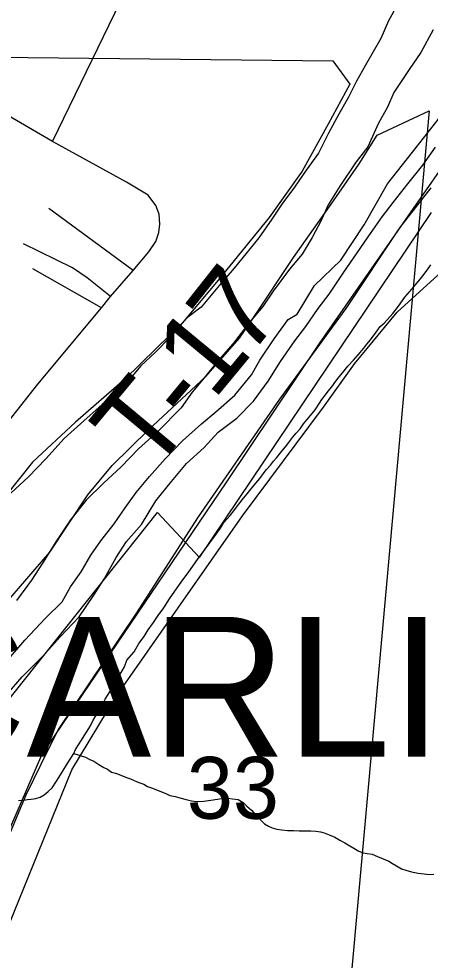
# Model space of a CAD drawing. Extents: x -7.3 to 34, y 0 to 22.
# Drawn here: x 6.491 to 6.77, y 19.077 to 19.714 of the extents above; entities that cross this region are included whole.
import ezdxf

# ---------------------------------------------------------------- set-up
doc = ezdxf.new("R2010")
doc.units = 0
for name, color, linetype in [('GM_X_Corporation', 7, 'Continuous'), ('GM_X_Corporation_Text', 7, 'Continuous'), ('GM_X_Major_River', 7, 'Continuous'), ('GM_X_Minor_River', 7, 'Continuous'), ('GM_X_Rail_Line', 7, 'Continuous'), ('GM_X_Section_Text', 7, 'Continuous'), ('GM_X_Township_Road', 7, 'Continuous'), ('GM_X_Township_Road_Text', 7, 'Continuous')]:
    doc.layers.add(name, color=color, linetype=linetype)

msp = doc.modelspace()

# ---------------------------------------------------------------- linework, layer by layer
at = {"layer": 'GM_X_Corporation'}
for points in [[(5.79575, 19.69545), (6.70378, 19.68552), (6.7152, 19.66976), (6.70064, 19.64278), (6.68296, 19.61094), (6.66075, 19.57958), (6.62618, 19.5371), (6.60174, 19.50805), (6.58435, 19.49097), (6.56271, 19.46982), (6.52956, 19.44095), (6.50061, 19.41388), (6.48197, 19.39077)], [(6.21496, 19.07117), (6.22873, 19.09665), (6.24704, 19.12166), (6.26369, 19.13988), (6.29063, 19.16131), (6.34976, 19.20102), (6.38311, 19.22119), (6.40198, 19.23633), (6.41972, 19.25226), (6.43441, 19.26712), (6.48124, 19.31692), (6.51227, 19.35305), (6.53804, 19.39192), (6.55435, 19.41166), (6.57907, 19.43578), (6.61767, 19.47174), (6.64054, 19.4978), (6.65029, 19.51199), (6.67724, 19.55236), (6.70415, 19.59083), (6.72169, 19.61585), (6.73382, 19.6353), (6.769, 19.65163), (6.71004, 18.99873)], [(5.99939, 18.48424), (6.1334, 18.89581), (6.16227, 18.87917), (6.36036, 19.15267), (6.43461, 19.19081), (6.58518, 19.37982), (6.61358, 19.34939), (6.77058, 19.58294)]]:
    msp.add_lwpolyline(points, dxfattribs=at)
at = {"layer": 'GM_X_Major_River'}
for points in [[(6.67957, 19.5142), (6.69125, 19.53359), (6.70914, 19.5506), (6.72493, 19.57451), (6.74082, 19.60221), (6.75769, 19.62381), (6.77495, 19.64578), (6.7927, 19.67229), (6.81129, 19.70144), (6.83018, 19.72793), (6.8476, 19.75597), (6.86566, 19.77981), (6.87518, 19.7959), (6.87566, 19.81411)], [(6.74739, 19.72317), (6.74143, 19.71269), (6.73618, 19.70067), (6.72586, 19.6827), (6.71989, 19.67184), (6.71429, 19.66097), (6.70792, 19.64936), (6.70077, 19.63663), (6.69397, 19.62313), (6.6857, 19.61157), (6.67782, 19.59999), (6.66917, 19.58844), (6.66246, 19.57836), (6.65379, 19.56566), (6.64479, 19.55488), (6.63695, 19.5452), (6.62717, 19.53368), (6.61465, 19.5188), (6.60459, 19.51108), (6.59364, 19.49844), (6.58351, 19.48806), (6.5738, 19.4792), (6.56205, 19.46506), (6.54771, 19.45289), (6.53528, 19.44181), (6.52208, 19.42999), (6.50959, 19.41625), (6.49789, 19.40401), (6.48585, 19.39292)], [(6.77161, 19.70662), (6.76324, 19.69126), (6.75536, 19.67969), (6.74509, 19.664), (6.74066, 19.65423), (6.73469, 19.64337), (6.72744, 19.62723), (6.7196, 19.61717), (6.70855, 19.60074), (6.70064, 19.58803), (6.69581, 19.57752), (6.68982, 19.5659), (6.68308, 19.55467), (6.67448, 19.54464), (6.66347, 19.52973), (6.65637, 19.51927), (6.64777, 19.50923), (6.63638, 19.49433), (6.62661, 19.48319), (6.61681, 19.4709), (6.6086, 19.46123), (6.60112, 19.45079), (6.58554, 19.43485), (6.57233, 19.42303), (6.56064, 19.41079), (6.5486, 19.3997), (6.53692, 19.38822), (6.52633, 19.37481), (6.51686, 19.36062), (6.50737, 19.34567), (6.49986, 19.33409), (6.48965, 19.32029)], [(6.48345, 19.25702), (6.49361, 19.26854), (6.50762, 19.28262), (6.51934, 19.29562), (6.53221, 19.30935), (6.54207, 19.32391), (6.54919, 19.33512), (6.55714, 19.34936), (6.56425, 19.36019), (6.57441, 19.37171), (6.58393, 19.3878), (6.59451, 19.40083), (6.60469, 19.4131), (6.61672, 19.42381), (6.62609, 19.43421), (6.63886, 19.44376), (6.65015, 19.45525), (6.65998, 19.46868), (6.6683, 19.48214), (6.67814, 19.49594), (6.6856, 19.50563), (6.69388, 19.51795), (6.70134, 19.52764), (6.71121, 19.54258), (6.71987, 19.55489), (6.72776, 19.56646), (6.73721, 19.5799), (6.74466, 19.58958), (6.75447, 19.60225), (6.76466, 19.6149), (6.77333, 19.62721)], [(6.52072, 19.31951), (6.52629, 19.32962), (6.53338, 19.3397), (6.54012, 19.35092), (6.54682, 19.36063), (6.55584, 19.37217), (6.56333, 19.383), (6.57081, 19.39345), (6.57981, 19.40423), (6.59036, 19.41612), (6.60205, 19.42836), (6.61486, 19.43981), (6.62456, 19.44792), (6.63737, 19.45937), (6.64872, 19.47314), (6.65429, 19.48287), (6.66415, 19.49743), (6.67359, 19.51048), (6.67957, 19.5142)], [(6.27448, 19.06705), (6.28426, 19.0782), (6.29135, 19.08866), (6.29961, 19.09985), (6.30862, 19.11102), (6.31839, 19.12216), (6.32703, 19.13334), (6.33524, 19.14301), (6.34541, 19.15491), (6.35866, 19.16863), (6.36995, 19.17974), (6.38387, 19.1904), (6.39436, 19.20001), (6.40402, 19.20661), (6.41841, 19.22068), (6.42809, 19.22803), (6.43856, 19.23726), (6.44823, 19.24424), (6.4607, 19.25721), (6.47041, 19.26609), (6.48288, 19.27906), (6.4954, 19.29356), (6.50943, 19.3084), (6.52072, 19.31951)]]:
    msp.add_lwpolyline(points, dxfattribs=at)
at = {"layer": 'GM_X_Minor_River'}
for points in [[(6.72096, 19.48665), (6.72485, 19.49113), (6.72681, 19.49374), (6.72915, 19.49673), (6.73305, 19.50197), (6.73579, 19.50571), (6.73849, 19.50793), (6.74433, 19.51465), (6.74823, 19.5195), (6.75253, 19.52549), (6.7572, 19.53109), (6.76188, 19.53669), (6.76461, 19.54005), (6.76695, 19.54304), (6.77008, 19.54753)], [(6.49101, 19.18495), (6.49443, 19.18525), (6.49709, 19.18558), (6.49975, 19.1859), (6.50279, 19.18621), (6.50585, 19.18728), (6.50854, 19.18875), (6.51124, 19.19097), (6.51395, 19.19357), (6.5167, 19.19807), (6.52063, 19.20407), (6.52456, 19.21044), (6.52849, 19.21682), (6.52968, 19.21945), (6.53362, 19.22583), (6.53558, 19.22883), (6.53872, 19.2337), (6.54029, 19.23633), (6.54149, 19.23896), (6.54306, 19.24159), (6.54582, 19.24647), (6.5474, 19.24909), (6.54977, 19.2536), (6.55291, 19.25848), (6.55529, 19.26337), (6.55843, 19.26824), (6.56118, 19.27274), (6.56276, 19.27537), (6.56437, 19.27989), (6.56943, 19.28548), (6.57258, 19.29111), (6.5761, 19.29598), (6.57886, 19.30048), (6.58238, 19.30534), (6.58552, 19.31022), (6.58942, 19.31545), (6.59334, 19.32145), (6.59687, 19.32669), (6.60118, 19.33268), (6.60626, 19.33979), (6.61213, 19.34802), (6.61799, 19.35588), (6.62307, 19.36261), (6.62776, 19.36934), (6.63012, 19.37309), (6.6344, 19.37794), (6.63674, 19.38093), (6.63869, 19.38355), (6.64103, 19.38654), (6.64337, 19.38953), (6.64571, 19.39252), (6.64844, 19.39588), (6.65156, 19.39961), (6.65429, 19.40297), (6.65663, 19.40596), (6.65897, 19.40895), (6.66169, 19.41193), (6.66364, 19.41455), (6.66597, 19.41716), (6.66831, 19.42015), (6.6726, 19.42538), (6.67455, 19.42799), (6.67651, 19.43061), (6.67885, 19.4336), (6.68157, 19.43658), (6.68392, 19.43995), (6.68625, 19.44256), (6.68859, 19.44555), (6.6917, 19.44929), (6.69484, 19.45378), (6.69641, 19.4564), (6.69875, 19.45939), (6.7007, 19.46201), (6.70304, 19.465), (6.70578, 19.46874), (6.70812, 19.47173), (6.71046, 19.47472), (6.71397, 19.47882), (6.71785, 19.48292), (6.72096, 19.48665)], [(6.52849, 19.21682), (6.5364, 19.21437), (6.5394, 19.21278), (6.54203, 19.21159), (6.54539, 19.20923), (6.54876, 19.20726), (6.55139, 19.20606), (6.55401, 19.20411), (6.5574, 19.20327), (6.56041, 19.20207), (6.56417, 19.20047), (6.5668, 19.19965), (6.56943, 19.19845), (6.57244, 19.19725), (6.57583, 19.19603), (6.57845, 19.19446), (6.58109, 19.19364), (6.58409, 19.19243), (6.58785, 19.19083), (6.59086, 19.18963), (6.59349, 19.18843), (6.59726, 19.18759), (6.60028, 19.18676), (6.60443, 19.18553), (6.6082, 19.18469), (6.61198, 19.18423), (6.61654, 19.18451), (6.62111, 19.18517), (6.62567, 19.18583), (6.62986, 19.18651), (6.63289, 19.18644), (6.63592, 19.18599), (6.6397, 19.18553), (6.64307, 19.18356), (6.64568, 19.18122), (6.64865, 19.1785), (6.65124, 19.1754), (6.65383, 19.17268), (6.65755, 19.16918), (6.66017, 19.16761), (6.6628, 19.16641), (6.66582, 19.16558), (6.66922, 19.16513), (6.67301, 19.16467), (6.67717, 19.16458), (6.68097, 19.1645), (6.68476, 19.16441), (6.68893, 19.16432), (6.69234, 19.16425), (6.69536, 19.1638), (6.698, 19.16299), (6.70139, 19.16178), (6.70515, 19.16017), (6.70852, 19.1582), (6.71189, 19.15623), (6.71526, 19.15425), (6.71788, 19.15268), (6.72125, 19.1507), (6.72426, 19.1495), (6.7269, 19.14906), (6.73031, 19.14861), (6.73407, 19.14701), (6.73782, 19.1454), (6.74158, 19.1438), (6.7442, 19.14223), (6.74682, 19.14065), (6.75019, 19.13868), (6.75321, 19.13785), (6.75698, 19.13663), (6.76151, 19.13577), (6.76567, 19.1353), (6.7687, 19.13486), (6.77212, 19.13516)]]:
    msp.add_lwpolyline(points, dxfattribs=at)
at = {"layer": 'GM_X_Rail_Line'}
for points in [[(5.86797, 17.82074), (5.95555, 17.97549), (6.08542, 18.19238), (6.10492, 18.22068), (6.19066, 18.52974), (6.2198, 18.58306), (6.37494, 18.91122), (6.50682, 19.2158), (6.63202, 19.40065), (6.69473, 19.49419), (6.79703, 19.64123), (6.94893, 19.86408), (6.97314, 19.90133), (7.00068, 19.98662)], [(6.23157, 18.56872), (6.25767, 18.62602), (6.30717, 18.73097), (6.35546, 18.82795), (6.3734, 18.85699), (6.38927, 18.87642), (6.41374, 18.91463), (6.45578, 19.03), (6.52725, 19.20568), (6.55721, 19.25523), (6.64261, 19.37772), (6.6974, 19.45125), (6.71851, 19.48043), (6.74726, 19.51536), (6.77489, 19.54041), (6.79714, 19.55888), (6.84936, 19.61297), (6.90337, 19.68298), (6.93396, 19.73922)]]:
    msp.add_lwpolyline(points, dxfattribs=at)
at = {"layer": 'GM_X_Township_Road'}
for p, q in [((6.56859, 19.54358), (6.51156, 19.58552)), ((6.54716, 19.51839), (6.50074, 19.54466))]:
    msp.add_line(p, q, dxfattribs=at)
for points in [[(6.51417, 19.63105), (6.55624, 19.71779), (6.57955, 19.76757), (6.59575, 19.80075), (6.60444, 19.82129), (6.60701, 19.83571), (6.60977, 19.95758)], [(6.47774, 19.43369), (6.484, 19.44131), (6.5042, 19.46674), (6.54716, 19.51839), (6.55338, 19.526), (6.56859, 19.54358), (6.57926, 19.55632), (6.5839, 19.56333), (6.58607, 19.56926), (6.58667, 19.57499), (6.58637, 19.5817), (6.58409, 19.58753), (6.57886, 19.59463), (6.56415, 19.60333), (6.51417, 19.63105), (6.43427, 19.6773), (6.42884, 19.68184)], [(6.36891, 18.88755), (6.39031, 18.93778), (6.40184, 18.96757), (6.41469, 18.99895), (6.42717, 19.02962), (6.43876, 19.0578), (6.46961, 19.12574), (6.49636, 19.18886), (6.51169, 19.22025), (6.51811, 19.23308), (6.57107, 19.3119), (6.61251, 19.37618), (6.6679, 19.45662), (6.71283, 19.51803), (6.74921, 19.5726), (6.77025, 19.59952)], [(6.55338, 19.526), (6.53758, 19.53874), (6.5276, 19.54545), (6.49452, 19.56165)]]:
    msp.add_lwpolyline(points, dxfattribs=at)

# ---------------------------------------------------------------- texts
at = {"layer": 'GM_X_Corporation_Text'}
msp.add_text('CARLISLE', height=0.094697, rotation=0.00001, dxfattribs=at).set_placement((6.40504, 19.21452))
at = {"layer": 'GM_X_Section_Text'}
msp.add_text('33', height=0.041856, rotation=0.00001, dxfattribs=at).set_placement((6.60503, 19.17261))
at = {"layer": 'GM_X_Township_Road_Text'}
for s, rotation, p in [('7', 51.70971, (6.64611, 19.48317)), ('1', 50.40826, (6.62292, 19.45511)), ('T', 50.25588, (6.58074, 19.40435)), ('-', 50.30838, (6.60795, 19.43707))]:
    msp.add_text(s, height=0.05682, rotation=rotation, dxfattribs=at).set_placement(p)

doc.saveas('drawing.dxf')
